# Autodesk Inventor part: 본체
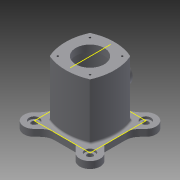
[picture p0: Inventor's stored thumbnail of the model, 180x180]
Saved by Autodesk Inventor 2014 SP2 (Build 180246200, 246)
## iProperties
Created: 2016-05
Part Number: 본체
Material: 일반
Document SubType Name: Modeling
Designer: apexhp001
Density: 1 g/cm^3
Appearance: 기본값
Author: apexhp001
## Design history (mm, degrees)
sketch "스케치1"
  geometry: L1 (-49, 49)-(49, 49); L2 (49, 49)-(49, -49); L3 (49, -49)-(-49, -49); L4 (-49, -49)-(-49, 49); 3 further points
  constraints: 8 end point, 2 midpoint, 2 parallel, 1 horizontal, 1 horizontal alignment, 1 perpendicular, 1 vertical alignment
  dimensions: "d0" = 98 distance of L2.end L3.end; "d1" = 98 distance of L1.end L2.end
extrude "돌출1" new body sketch "스케치1" distance "d2" = 12; taper "d3" = 0 deg
sketch "스케치2"
  geometry: L1 (49, 49)-(-49, 49) reference; L2 (-49, 49)-(-49, -49) reference; L3 (49, -49)-(49, 49) reference; L4 (-61.728, 36.272)-(-49, 23.544); L5 (-36.272, 61.728)-(-23.544, 49); L6 (-49, 23.544)-(-49, 49); L7 (-49, 49)-(-23.544, 49); A1 r 18 centre (-49, 49) between (-36.272, 61.728) and (-61.728, 36.272); 1 further point
  constraints: 8 end point, 2 parallel, 2 point on circle, 2 point on line, 2 tangent, 1 centre point, 1 coincident, 1 collinear
  dimensions: "d4" = 36 diameter of A1
extrude "돌출2" join sketch "스케치2" distance "d6" = 12; taper "d7" = 0 deg
sketch "스케치3"
  geometry: C1 r 25 at (0, 0); 1 further point
  constraints: 1 centre point, 1 coincident
  dimensions: "d8" = 50 diameter of C1
extrude "돌출3" cut sketch "스케치3" distance "d9" = 12; taper "d10" = 0 deg
fillet "모깎기1" dims "d11" = 25
sketch "스케치4"
  geometry: L1 (49, 49)-(-13.189, 49) reference; L2 (-30.866, 56.322)-(-36.272, 61.728) reference; L3 (-61.728, 36.272)-(-56.322, 30.866) reference; L4 (-49, 13.189)-(-49, -49) reference; L5 (-49, -49)-(49, -49) reference; L6 (49, -49)-(49, 49) reference; C1 r 25 at (0, 0) reference; A1 r 25 centre (-13.189, 74) between (-30.866, 56.322) and (-13.189, 49) reference; A2 r 18 centre (-49, 49) between (-36.272, 61.728) and (-61.728, 36.272) reference; A3 r 25 centre (-74, 13.189) between (-49, 13.189) and (-56.322, 30.866) reference
fillet "모깎기2" dims "d12" = 25
sketch "스케치5"
  geometry: L1 (49, 49)-(-13.189, 49) reference; L2 (49, -49)-(49, 49) reference; L3 (23.544, 49)-(49, 49); L4 (49, 49)-(49, 23.544); L5 (36.272, 61.728)-(23.544, 49); L6 (61.728, 36.272)-(49, 23.544); A1 r 25 centre (-13.189, -74) between (-13.189, -49) and (-30.866, -56.322) reference; A2 r 18 centre (49, 49) between (61.728, 36.272) and (36.272, 61.728)
  constraints: 8 end point, 3 point on circle, 2 point on line, 1 centre point, 1 coincident, 1 collinear, 1 tangent
  dimensions: "d13" = 36 diameter of A2
extrude "돌출4" join sketch "스케치5" distance "d14" = 12; taper "d15" = 0 deg
fillet "모깎기3" dims "d16" = 25
fillet "모깎기4" dims "d17" = 25
sketch "스케치6"
  geometry: L1 (-13.189, -49)-(49, -49) reference; L2 (49, -49)-(49, 13.189) reference; L3 (36.272, -61.728)-(23.544, -49); L4 (61.728, -36.272)-(49, -23.544); L5 (49, -23.544)-(49, -49); L6 (49, -49)-(23.544, -49); A1 r 18 centre (49, -49) between (36.272, -61.728) and (61.728, -36.272)
  constraints: 8 end point, 2 collinear, 2 point on circle, 2 point on line, 2 tangent, 1 centre point, 1 coincident, 1 parallel
  dimensions: "d18" = 36 diameter of A1
extrude "돌출5" cut sketch "스케치6" distance "d19" = 12; taper "d20" = 0 deg
sketch "스케치7"
  geometry: L1 (-13.189, -49)-(49, -49) reference; L2 (49, -49)-(49, 13.189) reference; L3 (36.272, -61.728)-(23.544, -49); L4 (61.728, -36.272)-(49, -23.544); L5 (31, -49)-(23.544, -49); L6 (49, -23.544)-(49, -49); L7 (49, -49)-(23.544, -49); A1 r 18 centre (49, -49) between (36.272, -61.728) and (61.728, -36.272)
  constraints: 10 end point, 2 collinear, 2 point on circle, 2 point on line, 2 tangent, 1 centre point, 1 coincident, 1 parallel
  dimensions: "d21" = 36 diameter of A1
extrude "돌출6" join sketch "스케치7" distance "d22" = 12; taper "d23" = 0 deg
sketch "스케치8"
  geometry: L1 (-30.866, -56.322)-(-36.272, -61.728) reference; L2 (61.728, -36.272)-(49, -23.544) reference; L3 (49, -23.544)-(49, 13.189) reference; L4 (56.322, 30.866)-(61.728, 36.272) reference; L5 (36.272, 61.728)-(30.866, 56.322) reference; L6 (-14.885, 14.885)-(-17.678, 17.678); L7 (-17.678, 17.678)-(0, 0); L8 (0, 0)-(17.678, -17.678); L9 (12.728, -12.728)-(0, 0); L10 (-17.678, -17.678)-(-35.355, -35.355); L11 (12.728, 12.728)-(17.678, 17.678); L12 (0, 0)-(-43, 0); L13 (20.085, 14.885)-(40.341, 14.885); L14 (0, 25)-(0, 43); L15 (0, 0)-(0, -43); A1 r 25 centre (0, 0) between (-17.678, 17.678) and (0, 25) reference; A2 r 85.579 centre (42.579, 0) between (-35.355, 35.355) and (-35.355, -35.355); A3 r 85.579 centre (0, -42.579) between (35.355, 35.355) and (-35.355, 35.355); A4 r 85.579 centre (-42.579, 0) between (35.355, -35.355) and (35.355, 35.355); A5 r 90.136 centre (0, 47.557) between (-35.355, -35.355) and (35.355, -35.355)
  constraints: 20 end point, 15 point on circle, 5 collinear, 4 centre point, 4 perpendicular, 4 point on line
  dimensions: "d24" = 50 distance of L7.end A2.start; "d25" = 50 distance of L7.end A4.start; "d26" = 50 distance of L7.end L10.end; "d27" = 50 distance of L7.end A3.start; "d28" = 43 distance of L7.end L12.end; "d29" = 43 distance of L7.end L13.end; "d30" = 43 distance of L7.end L14.end; "d31" = 43 distance of L7.end L15.end
extrude "돌출7" join sketch "스케치8" distance "d32" = 98; taper "d33" = 0 deg
sketch "스케치9"
  geometry: L1 (-35.355, 12)-(35.355, 12) reference; L2 (-35.355, 12)-(-35.355, 110) reference; L3 (35.355, 110)-(-35.355, 110) reference; L4 (35.355, 12)-(35.355, 110) reference; L5 (35.355, 12)-(35.355, 12) reference; L6 (35.355, 12)-(35.355, 110) reference; L7 (35.355, 110)-(35.355, 110) reference; L8 (35.355, 12)-(35.355, 110) reference; 1 further point
  node "투영된 루프1"
  node "투영된 루프2"
sketch "스케치10"
  geometry: C1 r 35 at (0, 0); 1 further point
  constraints: 1 centre point, 1 coincident
  dimensions: "d36" = 70 diameter of C1
extrude "돌출8" cut sketch "스케치10" distance "d37" = 86; taper "d38" = 0 deg
sketch "스케치11"
  geometry: 1 further point
fillet "모깎기5" dims "d39" = 3
fillet "모깎기6" dims "d40" = 3
node "작업 평면1"
sketch "스케치12"
  geometry: L1 (-65.971, 12)-(-29.437, 12) reference; L2 (-29.437, 12)-(-29.437, 0) reference; L3 (-29.437, 0)-(-65.971, 0) reference; L4 (-65.971, 0)-(-65.971, 12) reference; L5 (29.437, 12)-(65.971, 12) reference; L6 (65.971, 12)-(65.971, 0) reference; L7 (65.971, 0)-(29.437, 0) reference; L8 (29.437, 0)-(29.437, 12) reference; L9 (34.285, 110)-(-34.285, 110) reference; L10 (-35.832, 110)-(-35.832, 15) reference; L11 (43, 15)-(43, 110) reference; L12 (-43, 15)-(-43, 110) reference; C1 r 20 at (0, 61); 1 further point
  constraints: 1 centre point
  dimensions: "d42" = 40 diameter of C1; "d43" = 49 distance from line of C1.centre L9; "d44" = 43 distance from line of L12 C1.centre
extrude "돌출9" join sketch "스케치12" stored distance "d45" = 86; taper "d46" = 10 deg
sketch "스케치13"
  geometry: C1 r 20 at (0, 0) reference; C2 r 15 at (0, 0); 1 further point
  constraints: 1 centre point, 1 coincident
  dimensions: "d47" = 30 diameter of C2
extrude "돌출10" cut sketch "스케치13" distance "d48" = 8; taper "d49" = 0 deg
sketch "스케치14"
  geometry: C1 r 15 at (0, 0) reference; C2 r 12.5 at (0, 0); 1 further point
  constraints: 1 centre point, 1 coincident
  dimensions: "d50" = 25 diameter of C2
extrude "돌출11" cut sketch "스케치14" distance "d51" = 30; taper "d52" = 0 deg
sketch "스케치15"
  geometry: A1 r 18 centre (-49, 49) between (-36.272, 61.728) and (-61.728, 36.272) reference; A2 r 18 centre (-49, -49) between (-61.728, -36.272) and (-36.272, -61.728) reference; A3 r 18 centre (49, -49) between (36.272, -61.728) and (61.728, -36.272) reference; A4 r 18 centre (49, 49) between (61.728, 36.272) and (36.272, 61.728) reference; 5 further points
  constraints: 4 coincident
hole "구멍1" sketch "스케치15" at (-49, 49), (49, 49), (49, -49), (-49, -49) diameter "d53" = 10; stored, may be unused: countersink angle "d57" = 90 deg, drill point angle "d59" = 118 deg; dims "d54" = 6, "d55" = 18, "d56" = 4, "d58" = 8
sketch "스케치16" dims "d60" = 40
  geometry: L1 (0, 0)-(28.284, 28.284); L2 (0, 0)-(40, 0); C1 r 25 at (0, 0) reference; 1 further point
  constraints: 4 end point, 2 coincident, 1 equal length, 1 horizontal, 3 other
  dimensions: "d61" = 45 deg angle of L2 L1
hole "구멍2" sketch "스케치16" at (28.284, 28.284) diameter "d62" = 3.242; stored, may be unused: countersink angle "d66" = 90 deg, drill point angle "d68" = 118 deg; dims "d63" = 7, "d64" = 18, "d65" = 4, "d67" = 10
sketch "스케치17" dims "d72" = 40
  geometry: L1 (36.272, 61.728)-(30.866, 56.322) reference; L2 (0, 0)-(28.284, 28.284); C1 r 25 at (0, 0) reference; 1 further point
  constraints: 2 coincident, 2 end point, 1 parallel, 3 other
hole "구멍3" sketch "스케치17" at (28.284, 28.284) diameter "d73" = 3.242; stored, may be unused: countersink angle "d77" = 90 deg, drill point angle "d79" = 118 deg; dims "d74" = 7, "d75" = 18, "d76" = 4, "d78" = 10
node "솔리드1"
mirror "대칭1"
pattern_circular "원형 패턴1" dims angle "d70" = 360 deg
pattern_circular "원형 패턴2" dims angle "d81" = 360 deg
node "절단 모서리 투영1"
other parameters: "d41" = 55
